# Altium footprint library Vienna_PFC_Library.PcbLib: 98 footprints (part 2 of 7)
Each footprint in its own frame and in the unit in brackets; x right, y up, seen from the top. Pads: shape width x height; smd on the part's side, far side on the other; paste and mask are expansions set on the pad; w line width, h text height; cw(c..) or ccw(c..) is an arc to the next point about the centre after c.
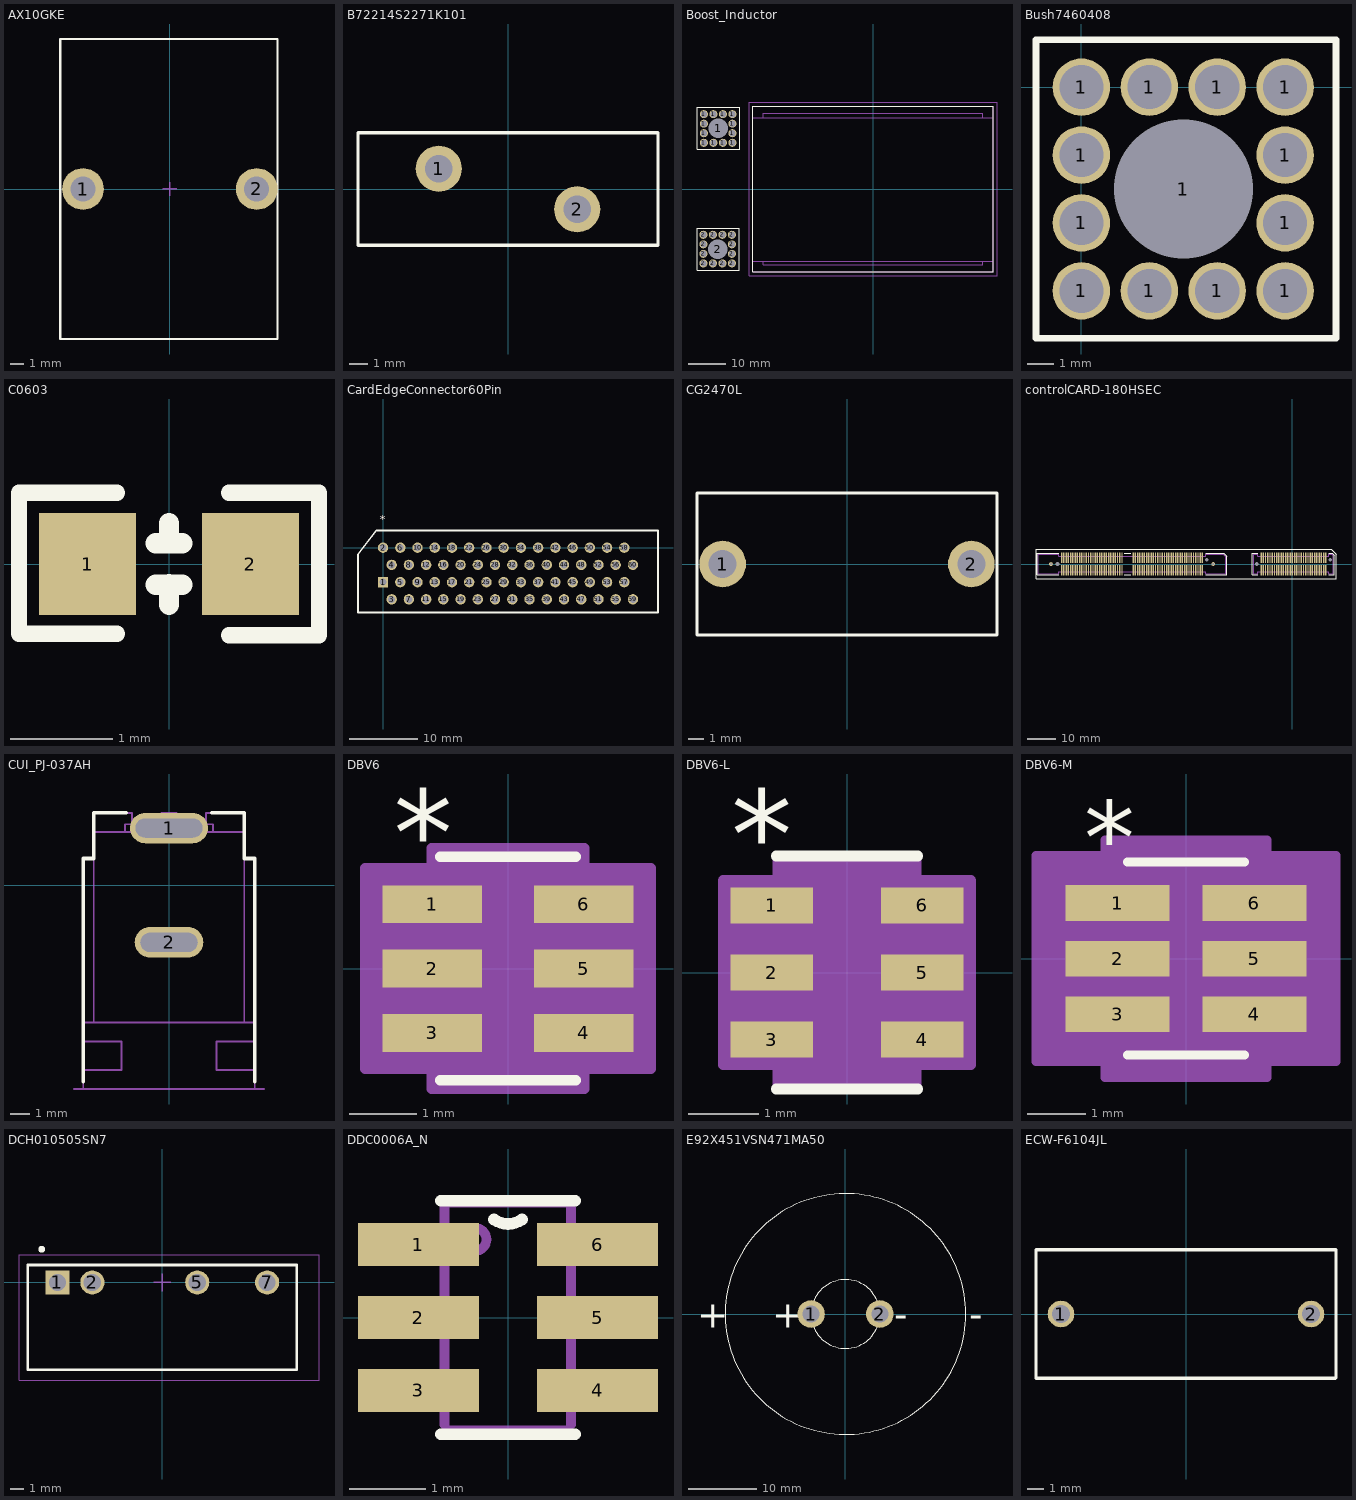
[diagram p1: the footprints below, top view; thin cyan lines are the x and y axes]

## AX10GKE [mm] "Res"
pads (2):
  round 3 hole 1.8: 1(-6.25,0) 2(6.25,0)
Top Overlay:
  lines w0.178: -7.874,-10.795 -7.874,10.795 7.747,10.795 7.747,-10.795 -7.874,-10.795
Mechanical 15:
  lines w0.1: -0.5,0 0.5,0 ; 0,-0.5 0,0.5
3D body "AX10GKE.stp": height 6.2, standoff -24.5, extent -7.535,-10.499 7.459,10.499

## B72214S2271K101 [mm] "Capacitor"
height 18.5
pads (2):
  round 2.5 hole 1.5: 1(-3.75,1.1) 2(3.75,-1.1)
Top Overlay:
  lines w0.178: -8.128,-3.048 8.128,-3.048 8.128,3.048 -8.128,3.048 -8.128,-3.048
3D body "User Library-S14K25 MOV.STEP": height 18.5, standoff -3, extent -7.75,-2.1 7.75,2.1

## Boost_Inductor [mm] "Boost_Inductor"
pads (26):
  round 2.15 hole 1.65: 1(-45.085,12.319) 1(-45.085,14.859) 1(-45.085,17.399) 1(-45.085,19.939) 1(-42.545,12.319) 1(-42.545,19.939) 1(-40.005,12.319) 1(-40.005,19.939) 1(-37.465,12.319) 1(-37.465,14.859) 1(-37.465,17.399) 1(-37.465,19.939) 2(-45.212,-19.812) 2(-45.212,-17.272) 2(-45.212,-14.732) 2(-45.212,-12.192) 2(-42.672,-19.812) 2(-42.672,-12.192) 2(-40.132,-19.812) 2(-40.132,-12.192) 2(-37.592,-19.812) 2(-37.592,-17.272) 2(-37.592,-14.732) 2(-37.592,-12.192)
  round 3.9 hole 5.2: 1(-41.275,16.129) 2(-41.402,-16.002)
Top Overlay:
  lines w0.1: -32.004,-22.098 32.004,-22.098 32.004,22.098 -32.004,22.098 -32.004,-22.098
  lines w0.254: -46.914,-21.59 -35.687,-21.59 -35.687,-10.414 -46.914,-10.414 -46.914,-21.59 ; -46.787,10.541 -46.787,21.717 -35.56,21.717 -35.56,10.541 -46.787,10.541
Mechanical 1:
  lines w0.1: 33.02,-5.969 33.02,23.114 21.59,23.114 -22.098,23.114 -33.02,23.114 -33.02,-23.114 -21.844,-23.114 21.844,-23.114 33.02,-23.114 33.02,-5.588
Mechanical 13:
  lines w0.013: -32.004,-19.191 31.996,-19.191 ; -32.004,19.009 31.996,19.009 ; -29.253,-19.191 -29.253,-20.191 29.244,-20.191 29.244,-19.191 ; -29.253,19.009 -29.253,20.209 29.244,20.209 29.244,19.009 ; -32.004,-22.091 -32.004,22.109 31.996,22.109 31.996,-22.091 -32.004,-22.091
3D body "Terminal.STEP": height 6, standoff -3.5, extent -45.673,11.629 -36.673,20.629
3D body "Terminal.STEP": height 6, standoff -3.5, extent -45.8,-20.502 -36.8,-11.502
3D body "Inductor_Mounting.STEP": height 71.62, standoff -7.38, extent -41,-22.102 41,22.098

## Bush7460408 [mm] "Power Connecter 12pin"
pads (13):
  round 2.15 hole 1.65: 1(0,-7.62) 1(0,-5.08) 1(0,-2.54) 1(0,0) 1(2.54,-7.62) 1(2.54,0) 1(5.08,-7.62) 1(5.08,0) 1(7.62,-7.62) 1(7.62,-5.08) 1(7.62,-2.54) 1(7.62,0)
  round 3.9 hole 5.2: 1(3.81,-3.81)
Top Overlay:
  lines w0.254: -1.702,-9.398 -1.702,1.778 9.525,1.778 9.525,-9.398 -1.702,-9.398
3D body "Terminal.STEP": height 6, standoff -3.5, extent -0.588,-8.31 8.412,0.69

## C0603 [mm]
height 1.45
pads (2):
  rect 0.95x1 smd: 1(-0.8,0) 2(0.8,0)
Top Overlay:
  lines w0.16: -0.51,-0.686 -1.473,-0.686 -1.473,0.7 -0.51,0.7 ; 0.59,-0.7 1.473,-0.7 1.473,0.7 0.59,0.7
  lines w0.2: -0.13,-0.203 0.13,-0.203 ; -0.13,0.203 0.13,0.203 ; 0,-0.4 0,-0.2 ; 0,0.203 0,0.403

## CardEdgeConnector60Pin [mil]
pads (60):
  rect 60x60 hole 40.16: 1(0,-200)
  round 60 hole 40.16: 2(0,0) 3(50,-300) 4(50,-100) 5(100,-200) 6(100,0) 7(150,-300) 8(150,-100) 9(200,-200) 10(200,0) 11(250,-300) 12(250,-100) 13(300,-200) 14(300,0) 15(350,-300) 16(350,-100) 17(400,-200) 18(400,0) 19(450,-300) 20(450,-100) 21(500,-200) 22(500,0) 23(550,-300) 24(550,-100) 25(600,-200) 26(600,0) 27(650,-300) 28(650,-100) 29(700,-200) 30(700,0) 31(750,-300) 32(750,-100) 33(800,-200) 34(800,0) 35(850,-300) 36(850,-100) 37(900,-200) 38(900,0) 39(950,-300) 40(950,-100) 41(1000,-200) 42(1000,0) 43(1050,-300) 44(1050,-100) 45(1100,-200) 46(1100,0) 47(1150,-300) 48(1150,-100) 49(1200,-200) 50(1200,0) 51(1250,-300) 52(1250,-100) 53(1300,-200) 54(1300,0) 55(1350,-300) 56(1350,-100) 57(1400,-200) 58(1400,0) 59(1450,-300) 60(1450,-100)
Top Overlay:
  lines w10: -145.28,-376 -145.28,-38 -39.37,100 1595.28,100 1595.28,-376 -145.28,-376
  text "*" at -20,136.33 h50

## CG2470L [mm] "Capacitor"
height 8.5
pads (2):
  round 3 hole 1.8: 1(-8,0) 2(8,0)
Top Overlay:
  lines w0.178: -9.652,-4.572 9.652,-4.572 9.652,4.572 -9.652,4.572 -9.652,-4.572
3D body: height 8.5, standoff 0, extent -2.794,-4.064 3.04,4.064

## controlCARD-180HSEC [mm] "Pads are not numbered according to datasheet."
height 7.13
pads (186):
  rect 0.5x3.724 smd: 1(-82.488,-2.211) 2(-82.488,2.205) 3(-81.688,-2.211) 4(-81.688,2.205) 5(-80.888,-2.211) 6(-80.888,2.205) 7(-80.088,-2.211) 8(-80.088,2.205) 9(-79.288,-2.211) 10(-79.288,2.205) 11(-78.488,-2.211) 12(-78.488,2.205) 13(-77.688,-2.211) 14(-77.688,2.205) 15(-76.888,-2.211) 16(-76.888,2.205) 17(-76.088,-2.211) 18(-76.088,2.205) 19(-75.288,-2.211) 20(-75.288,2.205) 21(-74.488,-2.211) 22(-74.488,2.205) 23(-73.688,-2.211) 24(-73.688,2.205) 25(-72.888,-2.211) 26(-72.888,2.205) 27(-72.088,-2.211) 28(-72.088,2.205) 29(-71.288,-2.211) 30(-71.288,2.205) 31(-70.488,-2.211) 32(-70.488,2.205) 33(-69.688,-2.211) 34(-69.688,2.205) 35(-68.888,-2.211) 36(-68.888,2.205) 37(-68.088,-2.211) 38(-68.088,2.205) 39(-67.288,-2.211) 40(-67.288,2.205) 41(-66.488,-2.211) 42(-66.488,2.205) 43(-65.688,-2.211) 44(-65.688,2.205) 45(-64.888,-2.211) 46(-64.888,2.205) 47(-64.088,-2.211) 48(-64.088,2.205) 49(-63.288,-2.211) 50(-63.288,2.205) 51(-62.488,-2.211) 52(-62.488,2.205) 53(-61.688,-2.211) 54(-61.688,2.205) 55(-60.888,-2.211) 56(-60.888,2.205) 57(-56.888,-2.211) 58(-56.888,2.205) 59(-56.088,-2.211) 60(-56.088,2.205) 61(-55.288,-2.211) 62(-55.288,2.205) 63(-54.488,-2.211) 64(-54.488,2.205) 65(-53.688,-2.211) 66(-53.688,2.205) 67(-52.888,-2.211) 68(-52.888,2.205) 69(-52.088,-2.211) 70(-52.088,2.205) 71(-51.288,-2.211) 72(-51.288,2.205) 73(-50.488,-2.211) 74(-50.488,2.205) 75(-49.688,-2.211) 76(-49.688,2.205) 77(-48.888,-2.211) 78(-48.888,2.205) 79(-48.088,-2.211) 80(-48.088,2.205) 81(-47.288,-2.211) 82(-47.288,2.205) 83(-46.488,-2.211) 84(-46.488,2.205) 85(-45.688,-2.211) 86(-45.688,2.205) 87(-44.888,-2.211) 88(-44.888,2.205) 89(-44.088,-2.211) 90(-44.088,2.205) 91(-43.288,-2.211) 92(-43.288,2.205) 93(-42.488,-2.211) 94(-42.488,2.205) 95(-41.688,-2.211) 96(-41.688,2.205) 97(-40.888,-2.211) 98(-40.888,2.205) 99(-40.088,-2.211) 100(-40.088,2.205) 101(-39.288,-2.211) 102(-39.288,2.205) 103(-38.488,-2.211) 104(-38.488,2.205) 105(-37.688,-2.211) 106(-37.688,2.205) 107(-36.888,-2.211) 108(-36.888,2.205) 109(-36.088,-2.211) 110(-36.088,2.205) 111(-35.288,-2.211) 112(-35.288,2.205) 113(-34.488,-2.211) 114(-34.488,2.205) 115(-33.688,-2.211) 116(-33.688,2.205) 117(-32.888,-2.211) 118(-32.888,2.205) 119(-32.088,-2.211) 120(-32.088,2.205) 121(-11.092,-2.208) 122(-11.092,2.208) 123(-10.292,-2.208) 124(-10.292,2.208) 125(-9.492,-2.208) 126(-9.492,2.208) 127(-8.692,-2.208) 128(-8.692,2.208) 129(-7.892,-2.208) 130(-7.892,2.208) 131(-7.092,-2.208) 132(-7.092,2.208) 133(-6.292,-2.208) 134(-6.292,2.208) 135(-5.492,-2.208) 136(-5.492,2.208) 137(-4.692,-2.208) 138(-4.692,2.208) 139(-3.892,-2.208) 140(-3.892,2.208) 141(-3.092,-2.208) 142(-3.092,2.208) 143(-2.292,-2.208) 144(-2.292,2.208) 145(-1.492,-2.208) 146(-1.492,2.208) 147(-0.692,-2.208) 148(-0.692,2.208) 149(0.108,-2.208) 150(0.108,2.208) 151(0.908,-2.208) 152(0.908,2.208) 153(1.708,-2.208) 154(1.708,2.208) 155(2.508,-2.208) 156(2.508,2.208) 157(3.308,-2.208) 158(3.308,2.208) 159(4.108,-2.208) 160(4.108,2.208) 161(4.908,-2.208) 162(4.908,2.208) 163(5.708,-2.208) 164(5.708,2.208) 165(6.508,-2.208) 166(6.508,2.208) 167(7.308,-2.208) 168(7.308,2.208) 169(8.108,-2.208) 170(8.108,2.208) 171(8.908,-2.208) 172(8.908,2.208) 173(9.708,-2.208) 174(9.708,2.208) 175(10.508,-2.208) 176(10.508,2.208) 177(11.308,-2.208) 178(11.308,2.208) 179(12.108,-2.208) 180(12.108,2.208)
  round 0.025 hole 1.27 unplated mask+0.876: 61(-12.592,0) 62(13.608,1.5) 181(-83.988,-0.003) 182(-30.588,1.496)
  round 1.348 hole 0.84: 185(-86.338,-0.003) 186(-28.238,-0.003)
Top Overlay:
  lines w0.254: -91.694,-3.952 -91.694,5.334 13.97,5.334 15.748,3.556 15.748,-3.444 ; -91.694,-3.81 -91.694,-5.334 15.748,-5.334 15.748,-3.556 ; -83.588,-3.884 -91.244,-3.884 -91.244,3.877 -83.588,3.877 ; -60.007,-3.884 -57.769,-3.884 ; -60.007,3.877 -57.769,3.877 ; -30.988,-3.884 -23.332,-3.884 -23.332,2.734 -24.475,3.877 -30.988,3.877 ; -12.192,-3.881 -14.173,-3.881 -14.173,3.881 -12.192,3.881 ; 13.173,-3.881 15.189,-3.881 15.189,3.119 14.427,3.881 13.198,3.881
Mechanical 5:
  lines w0.1: -90.863,-3.503 -90.863,3.497 -83.588,3.497 -83.588,2.797 -30.988,2.797 -30.988,3.497 -24.688,3.497 -23.713,2.522 -23.713,-3.503 -30.988,-3.503 -30.988,-2.803 -83.588,-2.803 -83.588,-3.503 -90.863,-3.503 ; -13.792,-3.468 -13.792,3.5 -12.192,3.5 -12.192,2.8 13.208,2.8 13.208,3.5 14.24,3.5 14.808,2.932 14.808,-3.5 13.208,-3.5 13.208,-2.8 -12.192,-2.8 -12.192,-3.5 -13.76,-3.5 -13.792,-3.468
  text ".Designator" at -1.075,-0.195 h1.02
  text ".Designator" at -60.231,-0.425 h1.02
3D body "HSEC8-130-01-L-DV-A.stp": height 7.95, standoff -1.35, extent -13.792,-3.5 14.808,3.5
3D body "Samtec-HSEC8-160-01-L-DV-A-BL.stp": height 12.35, standoff -1.35, extent -90.881,-3.5 -23.831,3.5

## CUI_PJ-037AH [mm] "Power Jack, 2mm, R/A, TH"
height 11.2
pads (2):
  oval 4.1x1.6 hole 1 slot 3.5 at 0 deg: 1(0,3)
  oval 3.6x1.6 hole 1 slot 3 at 0 deg: 2(0,-3)
Top Overlay:
  lines w0.2: -4.5,-10.3 -4.5,-9.7 -4.5,-8.2 -4.5,-7.2 -4.5,1.4 -3.95,1.4 -3.95,2.8 -3.95,3.8 -2.25,3.8 ; 2.25,3.8 3.95,3.8 3.95,2.8 3.95,1.4 4.5,1.4 4.5,-7.2 4.5,-8.2 4.5,-9.7 4.5,-10.3
Mechanical 1:
  lines w0.1: -5,-10.7 5,-10.7
  text "Board Edge" at 1.9,-11.8 h0.7
Mechanical 5:
  lines w0.1: -3.95,-7.2 -3.95,1.4 ; -2.3,2.8 -2.3,3.2 2.3,3.2 2.3,2.8 ; -1.95,3.2 -1.95,3.8 -3.95,3.8 -3.95,2.8 ; -1.5,3.2 cw(c-1.3,3.2) -1.3,3.4 1.3,3.4 cw(c1.3,3.2) 1.5,3.2 ; -0.4,3.4 -0.4,3.656 -0.4,3.8 0.4,3.8 0.4,3.656 0.4,3.4 ; 1.95,3.2 1.95,3.8 3.95,3.8 3.95,2.8 ; 3.95,-7.2 3.95,1.4 ; -4.5,-9.7 -4.5,-10.7 -4.2,-10.7 4.2,-10.7 4.5,-10.7 4.5,-9.7 ; -4.5,-9.7 -4.5,-8.2 ; -4.5,-9.7 -4.2,-9.7 -2.5,-9.7 -2.5,-8.2 -4.2,-8.2 -4.5,-8.2 ; -4.5,-8.2 -4.5,-7.2 ; -4.5,-7.2 -4.5,1.4 -3.95,1.4 ; -4.5,-7.2 -4.2,-7.2 4.2,-7.2 4.5,-7.2 ; -3.95,1.4 -3.95,2.8 ; -3.95,2.8 3.95,2.8 ; 3.95,1.4 4.5,1.4 4.5,-7.2 ; 3.95,1.4 3.95,2.8 ; 4.5,-9.7 4.5,-8.2 ; 4.5,-9.7 4.2,-9.7 2.5,-9.7 2.5,-8.2 4.2,-8.2 4.5,-8.2 ; 4.5,-8.2 4.5,-7.2
3D body "PJ-037AH.stp": height 11, standoff -3.5, extent -4.5,-10.7 4.5,3.8

## DBV6 [mil]
pads (6):
  rect 58x22 smd paste+0 mask+0: 1(-44,37.4) 2(-44,0) 3(-44,-37.4) 4(44,-37.4) 5(44,0) 6(44,37.4)
Top Overlay:
  lines w6: -39.5,-65 39.5,-65 ; -39.5,65 39.5,65
  text "*" at -66.5,54.4 h50
Mechanical 13:
  lines w0: -12,60 ccw(c0,60) 12,60
  lines w1: -59,-47.4 -34.5,-47.4 -34.5,-27.4 -59,-27.4 -59,-47.4 ; -59,-10 -34.5,-10 -34.5,10 -59,10 -59,-10 ; -59,27.4 -34.5,27.4 -34.5,47.4 -59,47.4 -59,27.4 ; -34.5,-60 -34.5,60 34.5,60 34.5,-60 -34.5,-60 ; 34.5,-47.4 59,-47.4 59,-27.4 34.5,-27.4 34.5,-47.4 ; 34.5,-10 59,-10 59,10 34.5,10 34.5,-10 ; 34.5,27.4 59,27.4 59,47.4 34.5,47.4 34.5,27.4
  text "*" at -32,7 h50
Mechanical 15:
  region: -44.5,-58.4 -83,-58.4 -83,58.4 -44.5,58.4 -44.5,70 44.5,70 44.5,58.4 83,58.4 83,-58.4 44.5,-58.4 44.5,-70 -44.5,-70
  lines w6: -83,-58.4 -44.5,-58.4 -44.5,-70 44.5,-70 44.5,-58.4 83,-58.4 83,58.4 44.5,58.4 44.5,70 -44.5,70 -44.5,58.4 -83,58.4 -83,-58.4
3D body: height 10, standoff 0, extent 0,0 10,10

## DBV6-L [mil]
pads (6):
  rect 46x20 smd paste+0 mask+0: 1(-42,37.4) 2(-42,0) 3(-42,-37.4) 4(42,-37.4) 5(42,0) 6(42,37.4)
Top Overlay:
  lines w6: -39.5,-65 39.5,-65 ; -39.5,65 39.5,65
  text "*" at -64.5,52.4 h50
Mechanical 13:
  lines w0: -12,60 ccw(c0,60) 12,60
  lines w1: -59,-47.4 -59,-27.4 -34.5,-27.4 -34.5,-47.4 -59,-47.4 ; -59,-10 -59,10 -34.5,10 -34.5,-10 -59,-10 ; -59,27.4 -59,47.4 -34.5,47.4 -34.5,27.4 -59,27.4 ; -34.5,-60 34.5,-60 34.5,60 -34.5,60 -34.5,-60 ; 34.5,-47.4 34.5,-27.4 59,-27.4 59,-47.4 34.5,-47.4 ; 34.5,-10 34.5,10 59,10 59,-10 34.5,-10 ; 34.5,27.4 34.5,47.4 59,47.4 59,27.4 34.5,27.4
  text "*" at -32,7 h50
Mechanical 15:
  region: -38.5,-51.4 -69,-51.4 -69,51.4 -38.5,51.4 -38.5,64 38.5,64 38.5,51.4 69,51.4 69,-51.4 38.5,-51.4 38.5,-64 -38.5,-64
  lines w6: -69,-51.4 -69,51.4 -38.5,51.4 -38.5,64 38.5,64 38.5,51.4 69,51.4 69,-51.4 38.5,-51.4 38.5,-64 -38.5,-64 -38.5,-51.4 -69,-51.4
3D body: height 10, standoff 0, extent 0,0 10,10

## DBV6-M [mil]
pads (6):
  rect 70x24 smd paste+0 mask+0: 1(-46,37.4) 2(-46,0) 3(-46,-37.4) 4(46,-37.4) 5(46,0) 6(46,37.4)
Top Overlay:
  lines w6: -39.5,-65 39.5,-65 ; -39.5,65 39.5,65
  text "*" at -68.5,56.4 h50
Mechanical 13:
  lines w0: -12,60 ccw(c0,60) 12,60
  lines w1: -59,-47.4 -59,-27.4 -34.5,-27.4 -34.5,-47.4 -59,-47.4 ; -59,-10 -59,10 -34.5,10 -34.5,-10 -59,-10 ; -59,27.4 -59,47.4 -34.5,47.4 -34.5,27.4 -59,27.4 ; -34.5,-60 34.5,-60 34.5,60 -34.5,60 -34.5,-60 ; 34.5,-47.4 34.5,-27.4 59,-27.4 59,-47.4 34.5,-47.4 ; 34.5,-10 34.5,10 59,10 59,-10 34.5,-10 ; 34.5,27.4 34.5,47.4 59,47.4 59,27.4 34.5,27.4
  text "*" at -32,7 h50
Mechanical 15:
  region: -54.5,-69.4 -101,-69.4 -101,69.4 -54.5,69.4 -54.5,80 54.5,80 54.5,69.4 101,69.4 101,-69.4 54.5,-69.4 54.5,-80 -54.5,-80
  lines w6: -101,-69.4 -101,69.4 -54.5,69.4 -54.5,80 54.5,80 54.5,69.4 101,69.4 101,-69.4 54.5,-69.4 54.5,-80 -54.5,-80 -54.5,-69.4 -101,-69.4
3D body: height 10, standoff 0, extent 0,0 10,10

## DCH010505SN7 [mm] "Module, 4-Leads, Body 19.56x7.62mm"
height 10.15
pads (4):
  rect 1.75x1.75 hole 1.25: 1(-7.62,0)
  round 1.75 hole 1.25: 2(-5.08,0) 5(2.54,0) 7(7.62,0)
Top Overlay:
  circle w0.25: c-8.761,2.413 r0.125
  lines w0.2: -9.78,-6.35 9.78,-6.35 9.78,1.27 -9.78,1.27 -9.78,-6.35
Mechanical 5:
  lines w0.1: -9.78,-6.35 9.78,-6.35 9.78,1.27 -9.78,1.27 -9.78,-6.35
Mechanical 15:
  lines w0.05: -10.41,-7.12 11.39,-7.12 11.39,2.02 -10.41,2.02 -10.41,-7.12
  lines w0.1: -0.635,0 0.635,0 ; 0,-0.635 0,0.635
3D body: height 10.15, standoff 0, extent -9.779,-6.35 9.779,1.27

## DDC0006A_N [mil]
pads (6):
  rect 62x22 smd paste+0 mask+2: 1(-46,37.4) 2(-46,0) 3(-46,-37.4) 4(46,-37.4) 5(46,0) 6(46,37.4)
Top Overlay:
  lines w6: -34.5,-60 34.5,-60 ; -34.5,60 34.5,60 ; -7.14,50.35 ccw(c0,60) 7.14,50.35
Mechanical 13:
  lines w5: -32.61,-54.94 -32.61,-54.79 -32.61,-44.68 ; -32.61,-28.94 -32.61,-7.28 ; -32.61,8.46 -32.61,30.12 ; -32.61,45.87 -32.61,55.97 -32.61,56.12 ; -31.55,-44.68 -35.55,-44.68 -44.42,-44.68 -45.63,-44.68 -49.26,-44.68 -56.58,-44.68 -56.58,-28.94 -49.26,-28.94 -45.63,-28.94 -44.42,-28.94 -35.55,-28.94 -31.55,-28.94 ; -31.55,-7.28 -35.55,-7.28 -44.42,-7.28 -45.63,-7.28 -49.26,-7.28 -56.58,-7.28 -56.58,8.46 -49.26,8.46 -45.63,8.46 -44.42,8.46 -35.55,8.46 -31.55,8.46 ; -31.55,30.12 -35.55,30.12 -44.42,30.12 -45.63,30.12 -49.26,30.12 -56.58,30.12 -56.58,45.87 -49.26,45.87 -45.63,45.87 -44.42,45.87 -35.55,45.87 -31.55,45.87 ; -29.68,-57.87 -29.53,-57.87 29.27,-57.87 29.42,-57.87 ; -29.68,59.06 -29.53,59.06 29.27,59.06 29.42,59.06 ; 31.29,-44.68 35.29,-44.68 44.16,-44.68 45.37,-44.68 49.01,-44.68 56.32,-44.68 56.32,-28.94 49.01,-28.94 45.37,-28.94 44.16,-28.94 35.29,-28.94 31.29,-28.94 ; 31.29,-7.28 35.29,-7.28 44.16,-7.28 45.37,-7.28 49.01,-7.28 56.32,-7.28 56.32,8.46 49.01,8.46 45.37,8.46 44.16,8.46 35.29,8.46 31.29,8.46 ; 31.29,30.12 35.29,30.12 44.16,30.12 45.37,30.12 49.01,30.12 56.32,30.12 56.32,45.87 49.01,45.87 45.37,45.87 44.16,45.87 35.29,45.87 31.29,45.87 ; 32.35,-54.94 32.35,-54.79 32.35,-44.68 ; 32.35,-28.94 32.35,-7.28 ; 32.35,8.46 32.35,30.12 ; 32.35,45.87 32.35,55.97 32.35,56.12 ; -22.77,40.07 ccw(c-16.91,40.07) -11.05,40.07 ccw(c-16.91,40.07) -22.77,40.07
3D body: height 10, standoff 0, extent 0,0 10,10

## E92X451VSN471MA50 [mm] "Capacitor"
height 55
pads (2):
  round 4 hole 2.5: 1(-5,0) 2(5,0)
Top Overlay:
  circle w0.1: c0,0 r17.5
  circle w0.1: c0,0 r5
  text "-" at 18.034,-2.032 h4
  text "-" at 7.112,-2.032 h4
  text "+" at -10.668,-2.032 h4
  text "+" at -21.59,-2.032 h4
3D body "35x50_Snap.stp": height 50, standoff -4.02, extent -24.626,-24.624 24.113,24.115

## ECW-F6104JL [mm] "PANASONIC"
height 13.6
pads (2):
  round 1.6 hole 1.1: 1(-7.5,0) 2(7.5,0)
Top Overlay:
  lines w0.2: -9,-3.85 -9,3.85 1.6,3.85 9,3.85 9,-3.8 8.95,-3.85 -9,-3.85
Mechanical 5:
  lines w0.1: 9,-3.85 -9,-3.85 -9,3.85 9,3.85 9,-3.825
3D body: height 4, standoff -2, extent 7.103,-0.399 7.9,0.399
3D body: height 4, standoff -2, extent -7.897,-0.399 -7.1,0.399
3D body: height 13.6, standoff 1.5, extent -9,-3.85 9,3.85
